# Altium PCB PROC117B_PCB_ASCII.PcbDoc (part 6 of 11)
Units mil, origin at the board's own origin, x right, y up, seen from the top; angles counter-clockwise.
Board outline 2480.32 x 3185.25 mil, 8 copper layers (Top Layer, L2_GND1, L3_SIG1, L4_PWR1, L5_PWR2, L6_SIG2, L7_GND2, Bottom Layer), stack 57.4 mil thick; 456 components, 292 nets, 7831 pads, 2905 vias.
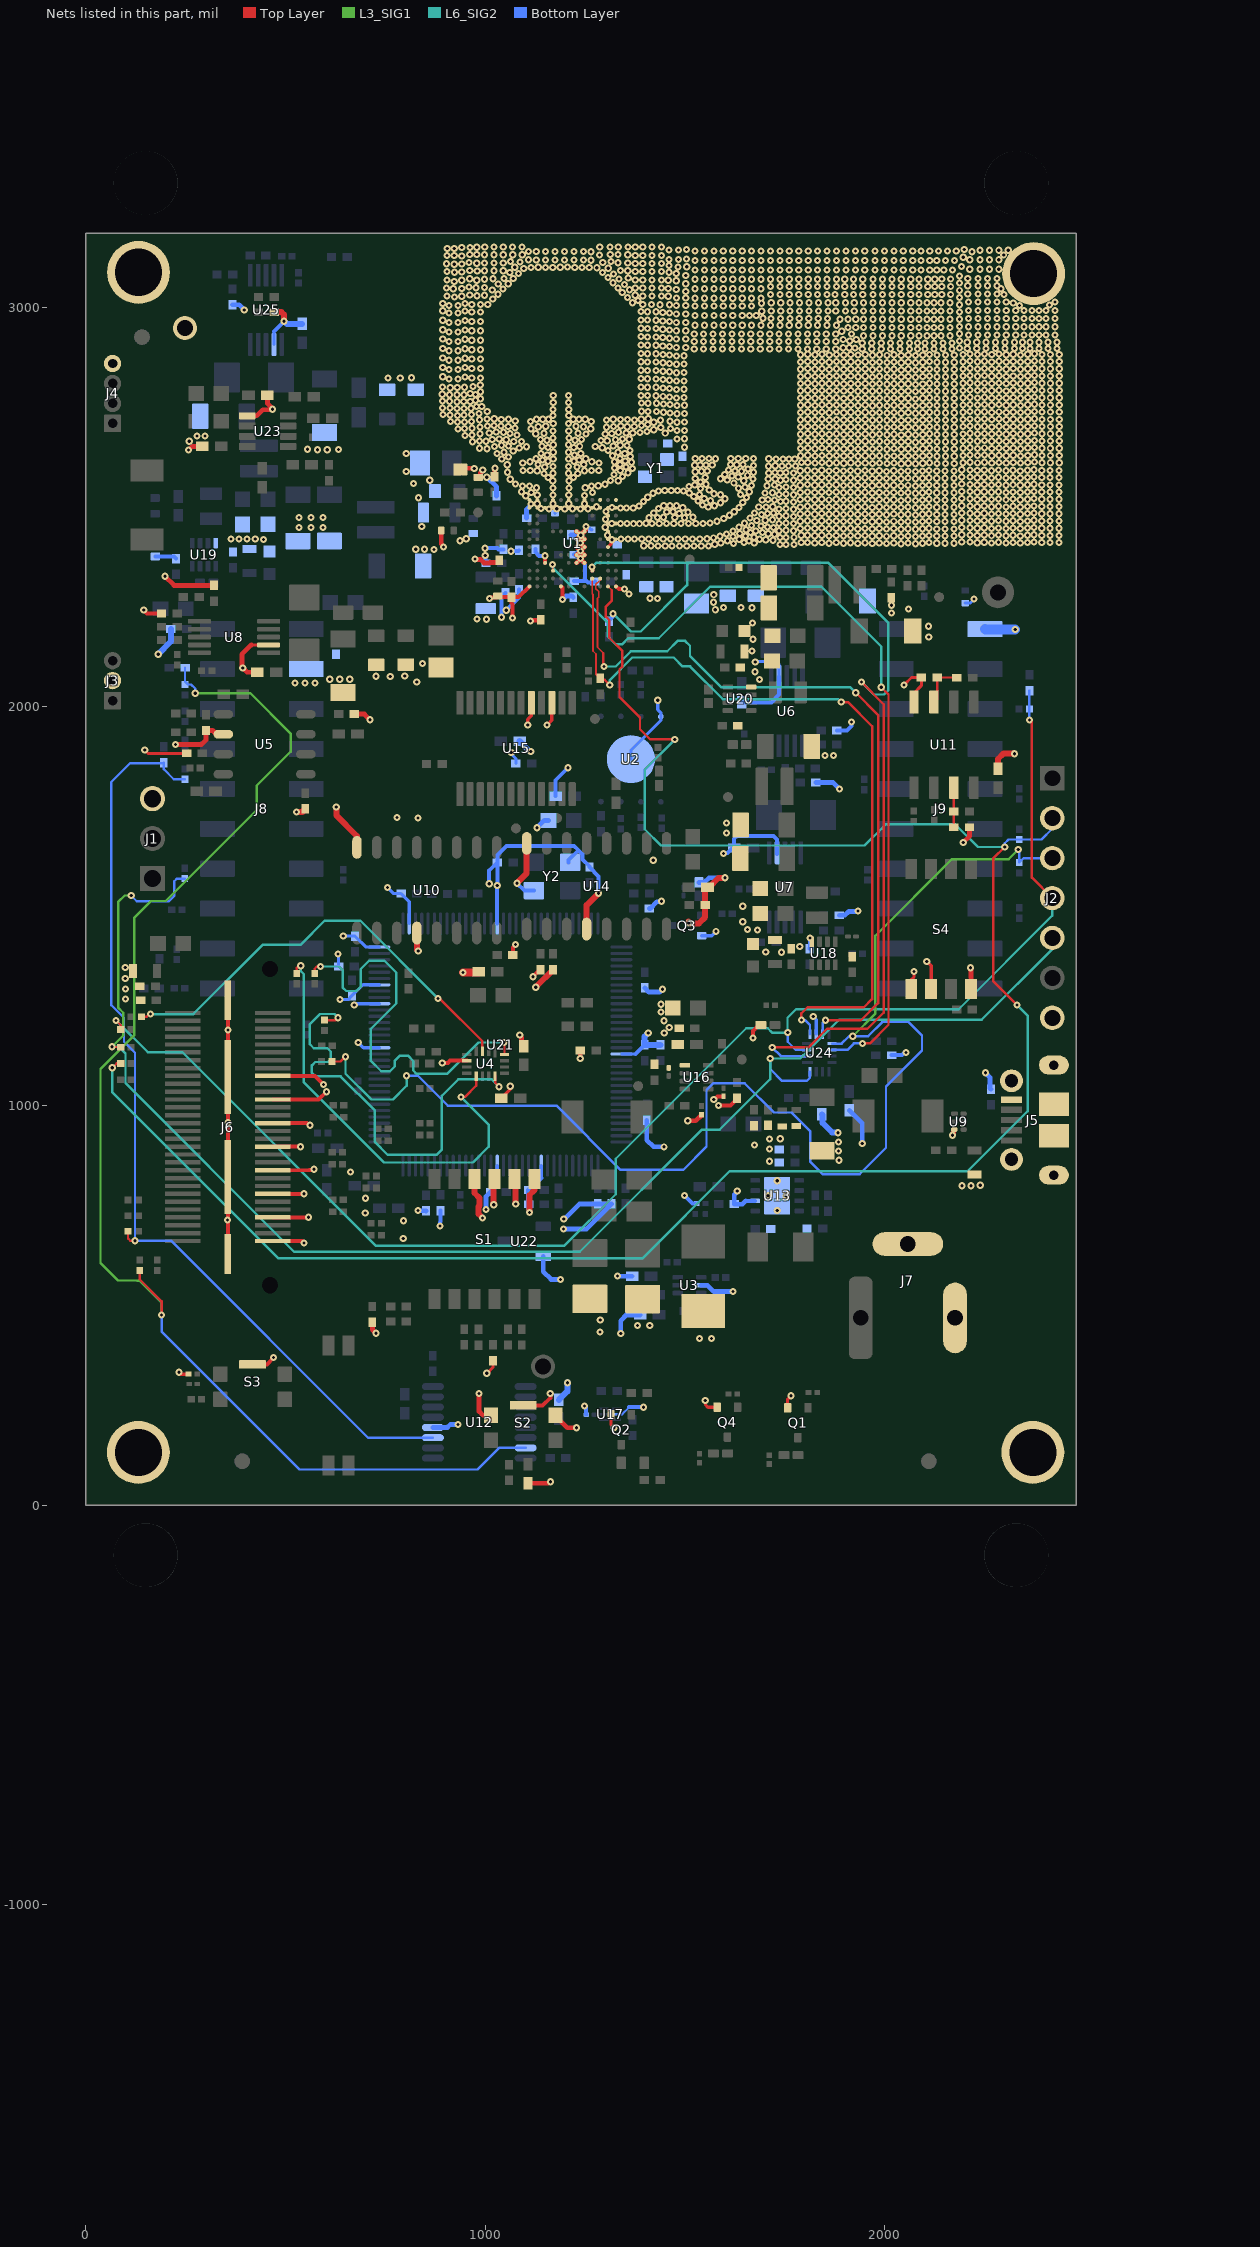
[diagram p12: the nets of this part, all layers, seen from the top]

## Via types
v1: diameter 18, hole 8, Top Layer to Bottom Layer, tented both sides, 2905 vias

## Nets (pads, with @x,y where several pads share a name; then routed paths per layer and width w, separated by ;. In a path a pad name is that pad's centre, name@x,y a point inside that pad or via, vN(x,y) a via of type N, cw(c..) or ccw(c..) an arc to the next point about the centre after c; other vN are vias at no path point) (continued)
DCA_LP_HOST_INTR_GPIO_0_LED: U1.J10 U24.10 | length 2189.6
  Top Layer w4: v1(1168.99,2355.28) 1168.97,2341.18 U1.J10@1170.05,2340.09
  Top Layer w6: v1(1944.68,1156.26) 1963.41,1156.26 2010.08,1202.93 2010.08,2029.8 v1(1991.83,2048.05)
  L6_SIG2 w6: v1(1168.99,2355.28) 1168.99,2348.04 1306.77,2210.26 1306.77,2176.04 1327.21,2155.6 1342.77,2155.6 1357.99,2170.82 1434.67,2170.82 1563.9,2300.05 1841.91,2300.05 1991.83,2150.13 v1(1991.83,2048.05)
  Bottom Layer w6: U24.10@1868.72,1140.1 1907.36,1140.1 1923.51,1156.26 v1(1944.68,1156.26)
DCA_LP_RS232_RX: R36.1 R61.1 R96.1 U12.3 | length 2393.1
  Top Layer w6: R61.1@105.65,686.13 105.65,667.89 111.44,662.1 122.94,662.1 v1(123.11,662.28)
  Bottom Layer w6: R36.1@248.36,1817.77 220.36,1817.77 195.06,1843.07 R96.1@195.06,1859.36 193.89,1858.18 111.24,1858.18 63.84,1810.79 63.84,1252.14 95.59,1220.39 95.59,1160.43 123.11,1132.91 v1(123.11,662.28) 213.53,662.28 706.94,168.86 U12.3@869.18,168.86
DCA_LP_RS232_TX: R35.1 R62.1 R95.1 U12.15 | length 3382.1
  Top Layer w6: R62.1@135.17,587.81 135.17,564.91 189.74,510.34 v1(189.74,476.22)
  L3_SIG1 w6: v1(189.74,476.22) 189.74,507.09 135.19,561.65 129.03,561.65 128.27,562.41 80.78,562.41 36.9,606.29 36.9,1092.15 121.06,1176.31 121.06,1470.58 163.31,1512.82 200.22,1512.82 427.95,1740.55 427.95,1801.75 513,1886.8 513,1932.1 412.07,2033.03 274.23,2033.03 v1(274.12,2032.93)
  Bottom Layer w6: v1(189.74,476.22) 189.74,434.55 534.95,89.34 980.78,89.34 1034.72,143.27 U12.15@1101.47,143.27 ; R95.1@248.55,2096.89 248.55,2062.57 256.19,2054.94 263.78,2054.94 274.12,2044.59 v1(274.12,2032.93)
DCA_LP_SPI_CLK: J2.5 R41.1 R146.1 U24.16 | length 3765.3
  Top Layer w6: v1(65.72,1147.92) 66.43,1147.2 86.8,1147.2 R41.1@87.52,1146.48
  L3_SIG1 w6: v1(65.72,1147.92) 93.94,1176.14 93.94,1232.98 80.95,1245.98 80.95,1510.25 97.37,1526.67 v1(113.77,1526.67)
  L6_SIG2 w6: v1(65.72,1147.92) 82.44,1147.92 99.31,1131.05 99.31,1056.82 521.73,634.4 1237.03,634.4 1542.95,940.33 1587.57,940.33 1714.04,1066.8 v1(1714.04,1118.37) 1789.34,1118.37 1886.92,1215.96 2243.71,1215.96 2420.67,1392.92 2420.67,1420.03 J2.5@2420.41,1420.3
  Bottom Layer w6: v1@113.77,1526.16 127.78,1512.14 208.16,1512.14 221.54,1525.52 221.54,1562.18 228.29,1568.93 R146.1@247.61,1568.93 ; v1(1714.04,1118.37) 1714.04,1091.97 1743.77,1062.24 1805.36,1062.24 1813.43,1070.32 1813.43,1084.81 U24.16@1813.6,1084.99
DCA_LP_SPI_CLK_I2C_SCL: R75.1 U1.D10 U24.2 | length 2666
  Top Layer w6: v1(1718.81,1146.13) 1809.89,1146.13 1856.53,1192.77 1957.59,1192.77 1998.13,1233.31 1998.13,2005.24 v1(1942.21,2061.17)
  Top Layer w10: v1(1267.99,2349.1) 1268.41,2348.69 1268.41,2340.16 U1.D10@1268.48,2340.09
  L6_SIG2 w6: v1(1267.99,2349.1) 1279.21,2360.31 1506.73,2360.31 ; v1(1320.35,2232.42) 1365,2187.76 1389.55,2187.76 1505.72,2303.93 1505.72,2359.3 1506.73,2360.31 ; v1(1942.21,2061.17) 1973.32,2030.05 1999.29,2030.05 2009.83,2040.6 2009.83,2209.21 1858.74,2360.31 1506.73,2360.31
  Bottom Layer w6: v1(1718.81,1146.13) 1740.59,1124.36 U24.2@1805.73,1124.36
  Bottom Layer w10: R75.1@1310.15,2213.57 1310.15,2215.54 1318.81,2224.21 1318.81,2230.89 v1(1320.35,2232.42)
DCA_LP_SPI_CS: J2.4 R39.1 R99.1 R140.2 U24.3 | length 3697.8
  Top Layer w6: v1(75.87,1213.57) 87.52,1201.92 R39.1@87.52,1191.19 ; v1(2362.9,1965.96) 2369.27,1959.58 2369.27,1571.44 J2.4@2420.41,1520.3
  L6_SIG2 w6: v1(75.87,1213.57) 155.52,1133.92 241.84,1133.92 725.74,650.03 1198.7,650.03 1327.12,778.45 1327.12,867.3 1653.97,1194.15 1707.77,1194.15 1718.72,1183.2 v1(1757.87,1183.2) 1757.2,1183.87 1757.2,1220.47 1778.66,1241.93 2186.17,1241.93 2420.41,1476.18 J2.4@2420.41,1520.3
  Bottom Layer w6: v1(1757.87,1183.2) 1757.87,1160.26 1778.03,1140.1 U24.3@1805.73,1140.1 ; v1(2362.9,1965.96) 2363.07,1966.13 R140.2@2363.07,1993.71 2363.07,2039.53 R99.1@2362.98,2039.62
DCA_LP_SPI_CS_I2C_SDA: R4.1 U1.D11 U24.5 | length 1994.7
  Top Layer w4: U1.D11@1268.48,2320.4 1268.48,2282.15 1270.23,2280.39 1270.23,2138.93 1277.64,2131.52
  Top Layer w6: 1277.64,2131.52 1277.64,2080.8 R4.1@1288.24,2070.19 1291.72,2066.72 1299.52,2066.72 v1(1312.25,2053.99) ; v1(1791.96,1214.7) 1791.96,1231.72 1807.23,1246.99 1948.89,1246.99 1969.17,1267.27 1969.17,1950.62 1908.84,2010.94 1891.94,2010.94 v1(1891.68,2011.2)
  L6_SIG2 w6: v1(1312.25,2053.99) 1312.39,2054.13 1312.39,2066.35 1368.56,2122.53 1472.29,2122.53 1494.45,2100.37 1513.33,2100.37 1595.14,2018.56 1884.32,2018.56 v1(1891.68,2011.2)
  Bottom Layer w6: v1(1791.96,1214.7) 1792.04,1214.61 1801.29,1214.61 1813.6,1202.31 U24.5@1813.6,1179.47
DCA_LP_SPI_MISO: J2.3 R53.2 R153.2 U24.9 | length 3361.7
  Top Layer w6: R53.2@616.38,1110.85 638.27,1110.85 650.32,1122.91 v1(650.47,1122.91)
  L3_SIG1 w6: v1(1920.55,1174.27) 1977.19,1230.91 1977.19,1425.84 2169.19,1617.84 2311.27,1617.84 v1(2335.12,1641.69)
  L6_SIG2 w6: v1(650.47,1122.91) 650.47,1080.39 715.07,1015.79 768.95,1015.79 803.44,1050.28 v1(803.44,1075.16)
  Bottom Layer w6: v1(803.44,1075.16) 831.81,1075.16 906.6,1000.36 1178.51,1000.36 1339.34,839.54 1496.16,839.54 1554.42,897.79 1554.42,1039.92 1570.68,1056.19 1650.22,1056.19 1723.24,983.17 1767.35,983.17 1814.68,935.84 1814.68,859.26 1844.88,829.06 1938.18,829.06 2004.02,894.91 2004.02,1048.7 2094.09,1138.76 2094.09,1176.19 2060,1210.27 1994.97,1210.27 1958.97,1174.27 v1(1920.55,1174.27) 1911.27,1174.27 1892.85,1155.85 U24.9@1868.72,1155.85 ; v1(2335.12,1641.69) 2337.72,1639.09 R153.2@2337.72,1609.25 2348.77,1620.3 J2.3@2420.41,1620.3
DCA_LP_SPI_MISO_REG_MODE: U1.C11 U24.7 | length 1948.9
  Top Layer w4: U1.C11@1288.16,2320.4 1288.16,2316.76 1277.24,2305.83 1277.24,2295.11 1284.43,2287.92 1284.43,2273.43 1281.49,2270.49 1281.49,2148.33 1296.01,2133.81
  Top Layer w6: 1296.01,2133.81 1296.01,2102.25 v1(1298.04,2100.22) ; v1(1852.7,1214.4) 1941.33,1214.4 1984.24,1257.31 1984.24,1978.36 v1(1928.01,2034.59)
  L6_SIG2 w6: v1(1298.04,2100.22) 1327.12,2100.22 1365.17,2138.26 1456,2138.26 1482.04,2164.31 1500.85,2164.31 1513.12,2152.03 1513.12,2126.69 1591.91,2047.9 1914.7,2047.9 v1(1928.01,2034.59)
  Bottom Layer w6: U24.7@1845.1,1179.47 1845.1,1206.97 1852.52,1214.4 v1(1852.7,1214.4)
DCA_LP_SPI_MOSI: J2.2 R52.1 R145.2 U1.B12 | length 5312
  Top Layer w4: U1.B12@1307.85,2300.72 1317.55,2291.02
  Top Layer w6: v1(66.37,1095.2) 77.85,1106.68 86.87,1106.68 R52.1@87.52,1106.03 ; 1317.55,2291.02 1317.55,2265.59 1302.35,2250.39 1302.35,2224.97 1310.85,2216.46 1310.85,2171.96 1343.67,2139.14 1343.67,2100.31 1336.53,2093.16 1336.53,2024.07 1387.84,1972.75 1387.84,1943.13 1413.39,1917.58 v1(1475.09,1917.58) ; v1(2301.12,1648.02) 2272.1,1618.99 2272.1,1312.66 v1(2332.2,1252.55)
  L6_SIG2 w6: v1(66.37,1095.2) 66.01,1094.84 66.01,1034.76 483,617.77 1393.73,617.77 1612.11,836.15 2208.27,836.15 2358.54,986.42 2358.54,1226.21 v1(2332.2,1252.55) ; v1(1475.09,1917.58) v1(1475.09,1917.58) 1399.58,1842 1399.58,1692.42 1440.22,1651.77 1950.32,1651.77 2003.39,1704.84 2177.37,1704.84 2234.2,1648.02 v1(2301.12,1648.02)
  Bottom Layer w6: v1(2301.12,1648.02) 2301.12,1657.58 2310.38,1666.84 R145.2@2337.72,1666.84 2393.54,1666.84 2420.41,1693.71 J2.2@2420.41,1720.3
DCA_TCK: R38.2 U4.16 | length 1050.4
  Top Layer w6: R38.2@573.4,1331.62 573.4,1343.13 579.23,1348.96 v1(587.84,1348.96) ; v1(1047.39,1158.6) 1048.51,1157.48 U4.16@1048.51,1128.64
  L6_SIG2 w6: v1(587.84,1348.96) 633.96,1348.96 643.26,1339.65 643.26,1296.54 652.28,1287.51 677.71,1287.51 688.16,1297.96 688.16,1342.08 709.32,1363.25 748.04,1363.25 777.94,1333.35 777.94,1256.85 714.04,1192.95 714.04,1112.57 739.97,1086.64 761.51,1086.64 774.04,1099.17 774.04,1113.16 786.48,1125.6 806.55,1125.6 819.85,1112.3 819.85,1088.29 828.09,1080.05 904.51,1080.05 983.07,1158.6 v1(1047.39,1158.6)
DCA_TDI: R37.1 U4.3 | length 1103.3
  Top Layer w6: R37.1@139.49,1223.18 152.37,1223.18 158.77,1229.58 v1(162.02,1229.58) ; v1(881.99,1268.92) 885.87,1268.92 993.02,1161.76 993.02,1136.89 U4.3@993.4,1136.51
  L6_SIG2 w6: v1(162.02,1229.58) 269.27,1229.58 442.52,1402.82 537.57,1402.82 598,1463.25 687.66,1463.25 v1(881.99,1268.92)
DCA_TDO: R34.2 U4.9 | length 1109.6
  Top Layer w6: R34.2@528.61,1331.62 528.61,1345.87 533.28,1350.54 v1(538.27,1350.54) ; v1(939.53,1022.2) 949.32,1022.2 977.65,1050.53 U4.9@977.65,1073.52
  L6_SIG2 w6: v1(538.27,1350.54) 538.27,1337.21 546.1,1329.38 546.1,1058.51 746.5,858.11 969.69,858.11 1008.85,897.27 1008.85,952.88 v1(939.53,1022.2)
DCA_TMS: R40.2 U4.12 | length 1118.6
  Top Layer w6: R40.2@597.77,1214.55 625.64,1214.55 v1(631.83,1220.73) ; U4.12@1024.89,1073.52 1024.89,1057.62 1034.89,1047.62 v1(1034.89,1047.54)
  L6_SIG2 w6: v1(631.83,1220.73) 622.54,1230.02 586.42,1230.02 561.1,1204.7 561.1,1153.96 570.78,1144.27 605.06,1144.27 613.57,1135.76 613.57,1116.92 606.25,1109.6 574.53,1109.6 566.17,1101.24 566.17,1082.1 574.74,1073.54 638.21,1073.54 723.86,987.89 723.86,909.38 756.03,877.21 878.47,877.21 891.83,890.57 891.83,1025.04 932.81,1066.02 1016.42,1066.02 v1(1034.89,1047.54)
EEPROM_A2: R161.1 R162.2 U11.3 | length 114.2
  Top Layer w6: U11.3@2123.96,2011.25 2131.84,2019.13 R162.2@2131.84,2072.49 2180.59,2072.49 R161.1@2181.24,2071.84
EEPROM_WPn: R157.1 R158.2 U11.7 | length 99.3
  Top Layer w6: R158.2@2173.7,1697.45 R157.1@2173.7,1737.31 2173.7,1796.42 U11.7@2173.96,1796.68
GND: C1.1 C2.2 C3.1 C4.1 C5.1 C6.2 C7.1 C8.1 C9.1 C10.1 C11.1 C12.1 C13.2 C14.1 C15.2 C16.1 C17.1 C18.1 C19.1 C20.1 C21.1 C22.1 C23.2 C24.1 C25.1 C26.1 C27.1 C28.1 C29.1 C30.2 C31.1 C32.1 C33.1 C34.2 C35.1 C36.2 C37.1 C38.1 C39.1 C40.2 C41.2 C42.2 C43.2 C44.2 C45.2 C46.1 C47.2 C48.2 C49.2 C50.2 C51.2 C52.1 C53.2 C54.1 C55.2 C56.2 C57.2 C58.2 C59.2 C60.2 C61.1 C62.2 C63.2 C64.1 C65.2 C66.2 C67.2 C68.1 C69.2 C70.2 C71.2 C72.2 C73.2 C74.2 C75.2 C76.2 C77.2 C78.1 C79.1 C80.1 C81.1 C82.1 C83.1 C84.2 C85.1 C86.1 C87.1 C88.2 C89.2 C90.2 C91.2 C92.2 C93.2 C94.2 C95.1 C96.1 C97.1 C98.1 C99.1 C101.1 C102.1 C103.1 C104.1 C105.1 C106.1 C107.1 C108.2 C109.2 C110.2 C111.1 C112.2 C113.1 C114.2 C115.2 C116.1 C118.1 C119.2 C120.2 C121.1 C122.1 C123.2 C124.1 C125.1 C126.1 C127.2 C128.2 C129.2 C130.1 C131.1 C132.2 C133.2 C134.2 C135.2 C136.2 C137.2 D4.2 D6.2 J1.3 J2.7 J3.2 J4.4 J5.5 J5.6 J5.7 J5.8 J5.9 J5.10 J5.11 J6.18 J6.24 J6.30 J6.36 J6.42 J6.48 J6.54 J6.60 J6.MP1 J6.MP2 J6.MP3 J6.MP4 J7.2 J7.3 J8.4 J9.2 pad.TH1 pad.TH2 pad.TH4 pad.TH9 Q1.2 Q2.2 Q3.2 Q4.2 R6.1 R11.1 R12.1 R33.1 R43.1 R57.2 R71.1 R72.1 R91.2 R101.1 R103.1 R113.1 R114.1 R116.1 R117.1 R120.1 R121.1 R131.1 R148.1 R150.1 R152.2 R158.1 R162.1 R177.1 R178.1 R180.1 R191.2 R194.2 R201.1 R205.1 R208.1 R215.2 R234.1 R239.1 S1.7 S1.8 S1.9 S1.10 S2.1 S2.2 S2.5 S3.5 S4.5 S4.6 S4.8 TP11.1 U1.A1 U1.A2 U1.A4 U1.A6 U1.A12 U1.B2 U1.B3 U1.B4 U1.B5 U1.B6 U1.B7 U1.C1 U1.C2 U1.D2 U1.E1 U1.E2 U1.E5 U1.E6 U1.E7 U1.E8 U1.E9 U1.F2 U1.F5 U1.F6 U1.F7 U1.F8 U1.F9 U1.G1 U1.G2 U1.H2 U1.H12 U1.J1 U1.J2 U1.K2 U1.K9 U1.L1 U1.L2 U1.M1 U1.M2 U1.M12 U2.4 U2.9 U3.2 U4.6 U5.2 U6.7 U7.7 U8.7 U9.3 U10.8 U10.12 U11.4 U12.4 U13.6 U13.9@1731.38,774.87 U14.8 U14.12 U15.3 U15.5 U16.1 U17.2 U18.8 U19.8 U20.8 U21.10 U21.17 U21.48 U21.55 U21.58 U21.64 U21.66 U21.80 U21.114 U22.2 U23.5 U24.6 U25.7 Y1.2 Y1.4 Y2.2 Y2.4 | length 10676
  Top Layer w8: v1(147.46,1890.73) 156.03,1882.16 252,1882.16 C37.1@252.79,1882.94 ; v1(233.45,332.65) 238.17,327.93 R215.2@257.37,327.93 ; 414.62,2154.08 U8.7@454.84,2154.08 ; v1(1004.31,330.03) 1004.97,330.03 1019.54,344.61 R208.1@1019.54,361.9 R208.1@1019.67,361.77 ; R6.1@1040.84,1019.14 1063.14,1041.45 v1(1063.14,1049.06) ; v1(1106.72,1953.37) 1106.63,1953.46 1106.63,1967.72 1115.82,1976.92 U15.5@1115.82,2009.1 ; v1(1155.01,1953.39) 1155.24,1953.39 1167,1965.14 U15.3@1167,2009.1 ; U1.B7@1307.85,2399.14 1307.85,2399.79 1315.82,2407.76 1315.82,2415.64 v1(1317.74,2417.55) ; Q2.2@1315.17,226.41 1315.17,201.12 v1(1322.52,193.78) ; v1(1551.48,261.63) 1552.2,260.9 1552.2,250.84 1557.84,245.2 Q4.2@1581.21,245.2 ; Q1.2@1757.47,243.61 1757.47,265.43 1766.01,273.98 v1(1766.01,274.05) ; v1(2048.84,2053.47) 2067.86,2072.49 R162.1@2092.47,2072.49 2092.47,2052.36 2073.96,2033.85 U11.4@2073.96,2011.25 ; S4.5@2067.14,1292.74 2067.03,1292.85 2067.03,1315.37 2073.97,1322.31 v1(2073.97,1336.47) ; v1@2106.34,1361.7 2117.14,1350.9 S4.6@2117.14,1292.74
  Top Layer w10: v1(144.91,2241.59) 153.69,2232.82 R116.1@189.51,2232.82 ; J6.MP4@355.62,629.36 J6.MP3@355.62,821.88 J6.MP2@355.62,1071.88 J6.MP1@355.62,1264.4 ; S3.5@417.49,352.46 453.46,352.46 470.07,369.07 v1(470.07,369.8) ; J6.60@468.42,661.44 541.24,661.44 v1(546.09,656.59) ; J6.54@468.42,720.5 557.79,720.5 v1(557.98,720.69) ; J6.48@468.42,779.55 546.4,779.55 v1(546.8,779.96) ; J6.42@468.42,838.61 558.84,838.61 559.78,839.55 569.62,839.55 v1(571.15,841.08) ; J6.36@468.42,897.66 537.72,897.66 v1(537.8,897.59) ; J6.30@468.42,956.72 554.02,956.72 559.36,951.38 v1(561.52,951.38) ; J6.24@468.42,1015.77 583.03,1015.77 v1(602.46,1035.21) ; J6.18@468.42,1074.83 574.15,1074.83 v1(595.34,1053.64) ; v1(892.85,1107.38) 906.87,1107.38 912.39,1112.89 U4.6@954.03,1112.89 ; v1(1010.9,2270.52) 1013.06,2270.52 1015.27,2272.74 1027.83,2272.74 C17.1@1031.69,2276.59 1034.64,2276.59 C17.1@1037.63,2273.6 ; C17.1@1038.5,2272.74 C17.1@1037.63,2273.6 ; v1(1068.7,2221.65) 1068.7,2256.68 1066.08,2259.29 C21.1@1066.08,2273.6 ; C88.2@1069.26,1377.59 1069.26,1396.63 1076.44,1403.81 v1(1076.44,1403.96) ; S2.5@1095.36,249.85 1144.17,249.85 1163.14,268.83 v1(1163.14,279.25) ; U1.M12@1111,2300.72 1083.88,2273.6 C21.1@1066.08,2273.6 ; v1(1119.71,1323.38) 1137.24,1340.91 C125.1@1138.59,1340.91 ; v1(1149.72,2377.41) 1150.3,2376.84 1150.3,2359.85 U1.K9@1150.37,2359.77 ; U1.H12@1190.49,2300.72 1193.67,2297.54 v1(1193.67,2267.68) ; v1(1238.14,1118.77) v1@1238.3,1118.93 ; C115.2@1238.3,1138.46 C115.2@1238.46,1138.62 ; U1.A12@1327.53,2300.72 1328.17,2300.72 1335.29,2293.61 1344.78,2293.61 v1@1346.69,2291.69 ; v1(1572.42,1015.4) 1574.04,1015.4 1581.4,1022.77 1595.94,1022.77 1596.77,1023.59 C50.2@1596.77,1023.74 ; v1(1584.55,1000.88) 1614.24,1000.88 1630.46,1017.09 C137.2@1630.46,1019.06 ; v1(1670.99,1169.88) 1670.99,1187.02 1686.34,1202.37 D6.2@1690.47,1202.37 ; C17.1@1037.63,2273.6 C21.1@1066.08,2273.6
  Top Layer w12: v1(198.25,2326.05) 221.09,2303.21 R117.1@321.43,2303.21 ; v1(224.65,1905.01) 289.91,1905.01 301.2,1916.3 C39.1@301.2,1939.79 ; v1(257.27,2641.93) 266.52,2651.2 C123.2@291.68,2651.2 ; C39.1@301.17,1939.82 317.55,1939.82 326.91,1930.45 U5.2@344.39,1930.45 ; U23.5@404.31,2727.79 427.64,2727.79 443,2743.15 466.57,2743.15 466.57,2747.07 454.71,2758.93 C132.2@454.71,2779.11 ; 414.62,2154.08 390.99,2130.45 390.99,2102.85 391.86,2101.98 391.86,2097.73 404.01,2085.59 C59.2@429.48,2085.59 ; R71.1@672.41,1980.88 697.62,1980.88 v1(711.57,1966.94) ; R205.1@717.37,458.04 717.68,457.73 717.68,439.42 726.77,430.33 v1(726.77,430.23) ; C3.1@890,2440.84 890,2406.99 895.74,2401.25 v1(895.74,2399.63) ; C23.2@937.73,2597.25 938.51,2596.47 972.05,2596.47 v1(972.83,2595.7) ; v1(974.42,2368.95) 975.57,2367.8 989.06,2367.8 997.44,2359.43 1010.84,2359.43 1012.25,2360.83 1031.39,2360.83 1035.23,2364.68 C26.1@1035.23,2366.65 ; C9.1@982.61,2573.88 985.56,2573.88 988.42,2576.74 988.42,2584.8 993.87,2590.25 v1(993.87,2591.88) ; v1(984.86,279.25) 984.83,234.55 994.14,225.24 S2.1@1014.65,225.24 ; C19.1@1023.28,2575.69 1023.98,2576.39 1023.98,2595.77 v1(1024.68,2596.47) ; v1(1086.66,1177.43) 1086.66,1175.81 1090.81,1171.66 1090.81,1155.37 C40.2@1096.63,1149.56 ; C53.2@1107.4,54.94 1158.29,54.94 1161.81,58.46 v1(1163.44,58.46) ; v1(1113.48,2214.32) 1114.87,2215.71 1138.04,2215.71 C7.1@1139.43,2217.11 ; S2.2@1176.07,224.1 1176.07,223.28 1187.78,211.56 1188.61,211.56 1206.18,193.99 v1(1228.56,193.99) ; U1.F9@1229.11,2359.77 1229.11,2359.82 1238.9,2369.62 v1@1238.9,2369.7 ; U1.F8@1229.11,2379.46 1229.11,2379.55 1238.86,2389.3 v1@1238.86,2389.5 ; U1.F5@1229.11,2438.51 U1.F5@1229.33,2438.51 ; U1.F8@1229.11,2379.46 v1@1238.9,2369.7 ; v1@1238.17,2409.73 1229.11,2418.79 1229.29,2418.83 v1@1239.13,2428.67 ; v1@1238.3,1118.93 C115.2@1238.3,1138.46 ; U1.E9@1248.79,2359.77 v1@1238.9,2369.7 ; v1(1252.48,2450.42) 1251.33,2449.27 1251.33,2441.05 U1.E5@1248.79,2438.51 1248.79,2438.33 1239.17,2428.71 v1(1239.36,2428.71) 1239.36,2428.49 1248.79,2419.06 U1.E6@1248.79,2418.83 1248.15,2418.83 1239.01,2409.69 v1(1238.17,2409.69) ; v1(1507.46,962.65) 1507.71,962.4 1520.32,962.4 ; 1522.46,962.4 1527.54,962.4 1541.9,976.75 R120.1@1541.9,977.54 ; R131.1@2017.19,2272.41 2017.33,2272.27 2017.33,2253.57 v1(2017.46,2253.43) ; v1(2170.48,926.11) 2170.48,927.74 2172.77,930.02 2172.77,940.51 2172.86,940.6 U9.3@2174.64,940.6 ; v1(2197.16,1659.6) 2213.07,1675.51 R158.1@2213.07,1697.45 ; v1(2215.39,1345.67) 2216.54,1344.53 2216.54,1320.84 2217.14,1320.24 S4.8@2217.14,1292.74 ; U1.F5@1229.33,2438.51 1239.13,2428.71 U1.F5@1229.33,2438.51 ; v1(1238.17,2409.69) 1248.75,2399.14 1248.7,2399.14 1239.21,2389.66 v1(1239.12,2389.66) v1@1238.86,2389.66 ; v1(1238.17,2409.69) 1238.21,2408.89 1229.11,2399.79 U1.F7@1229.11,2399.14 1229.37,2399.14 v1@1238.86,2389.66 ; v1@1238.86,2389.5 v1@1238.86,2389.66 ; v1@1238.86,2389.5 1248.79,2379.56 U1.E8@1248.79,2379.46 1248.74,2379.46 1238.98,2369.7 v1@1238.9,2369.7
  Top Layer w15: R148.1@471.89,2987.41 490.04,2987.41 496.26,2981.19 v1(496.26,2964.48) ; v1(527.69,1735.67) 528.26,1736.24 542.25,1736.24 545.4,1739.39 547.37,1739.39 549.71,1741.73 C38.1@549.71,1743.7 ; v1(627.33,1748) 627.33,1727.18 679.03,1675.48 U10.8@679.03,1647.18 ; U10.12@829.03,1432.62 828.92,1432.5 828.92,1391.34 v1(832.73,1387.53) ; S1.10@973.28,816.28 973.28,781.68 986.2,768.76 986.2,750.12 983.59,747.52 983.59,729.05 v1(993.61,719.03) ; v1(1021.59,752.2) 1021.59,814.59 S1.9@1023.28,816.28 ; S1.8@1073.28,816.28 1076.52,813.04 v1(1076.52,754.22) ; v1(1079.52,1557.19) 1104.22,1581.9 U14.8@1104.22,1657.18 ; v1(1111.18,732.94) 1111.18,776.68 1123.28,788.78 S1.7@1123.28,816.28 ; v1(1126.68,1297.08) 1126.68,1297.54 C124.1@1170.32,1341.17 ; U14.12@1254.22,1442.61 1254.22,1502.29 v1(1284.32,1532.38) ; v1(1509.88,1457.51) 1509.88,1461.41 1514.27,1457.02 1535.76,1457.02 1551.03,1472.3 C90.2@1551.03,1502.8 1551.03,1543.07 1555.34,1547.38 C89.2@1556.89,1547.38 1560.82,1547.38 1583.84,1570.4 1600.48,1570.4 v1(1601.06,1570.97) ; C65.2@2284.36,1843.87 2284.36,1868.55 2297.56,1881.75 v1(2325.76,1881.75)
  Top Layer w20: v1(944.63,1334.11) 982.37,1334.11 C75.2@983.55,1335.29
  Bottom Layer w6: U17.2@1328.64,227.49 1343.11,227.49 1360.92,245.3
  Bottom Layer w8: U25.7@471.17,2906.62 471.17,2939.39 ; v1(631.31,1379.88) 633.04,1378.15 R194.2@633.04,1348.51 ; v1(636.57,1266.08) 657.43,1266.08 R234.1@666.49,1275.15 694.27,1302.92 U21.58@735.06,1302.92 ; v1(644.86,1425.53) 651.9,1425.53 652.37,1425.07 R191.2@674.18,1425.07 701.83,1397.41 U21.64@735.06,1397.41 ; v1(672.2,1252.06) 675.81,1255.67 U21.55@735.06,1255.67 ; v1(682.29,1158.3) 695.16,1145.44 U21.48@735.06,1145.44 ; v1(755.84,1546.31) 770.7,1531.47 C95.1@789.57,1531.47 809.87,1511.18 U21.66@809.87,1456.46 ; 1030.34,800.99 U21.17@1030.34,850.16 ; v1(1065.3,1884.79) 1065.3,1881.48 1077.05,1869.73 R91.2@1077.05,1857.39 ; C99.1@1108.96,753.63 C99.1@1108.87,753.54 C99.1@1110.03,752.38 ; C102.1@1108.96,789.42 C102.1@1110.47,789.42 ; v1@1110.03,734.09 v1(1111.18,732.94) ; 1140.58,819.52 U21.10@1140.58,850.16 ; C22.1@1174.63,2483.89 1177.33,2486.59 1177.33,2493.11 v1(1179.24,2495.02) ; v1(1252.48,2450.42) 1254.39,2448.51 1259.12,2448.51 1265.15,2442.47 C18.1@1267.12,2442.47 ; U21.114@1341.36,1129.69 1376.79,1129.69 ; U2.9@1365.12,1868.19 1365.12,1889.77 1440.12,1964.77 U2.4@1440.12,1974.49 1440.12,1984.22 1432.24,1992.09 v1(1432.24,2015.56) ; C126.1@1438.64,1152.5 C126.1@1438.99,1152.86 ; Q3.2@1542.43,1425.91 1567.39,1425.91 v1(1578.35,1436.88) ; v1(1676.27,2111.72) 1677.16,2112.61 1729.2,2112.61 1735.92,2105.89 U6.7@1735.92,2074.85 ; v1(1821.61,1223.93) 1829.35,1216.2 U24.6@1829.35,1179.47 ; C78.1@2202.3,2258.84 2202.37,2258.91 2214.34,2258.91 v1(2224.49,2269.05)
  Bottom Layer w10: R121.1@174.34,2375.85 220.74,2375.85 225.59,2371.01 R178.1@225.59,2370.27 ; 471.17,2939.39 v1(496.26,2964.48) ; v1(886.85,699) 886.85,708.38 888.65,710.18 C113.1@888.65,737.61 ; v1(999.92,2396.26) 1031.08,2396.26 1033.74,2393.59 C12.1@1046.09,2393.59 ; v1(1000.2,2377.88) 1001.18,2376.9 1001.18,2359.65 C8.1@1002.15,2358.67 ; v1(1010.12,1556.13) 1010.12,1588.66 C98.1@1030.67,1609.21 ; U21.80@1030.34,1456.46 v1(1030.32,1551.43) 1030.67,1551.77 C98.1@1030.67,1609.21 ; v1(1040.85,2223.4) 1040.85,2273.85 C30.2@1051.43,2284.43 ; v1(1052.71,2240.84) 1084.65,2272.78 C25.1@1084.65,2292.85 ; v1(1064.67,2388.54) 1066.01,2389.88 1083.45,2389.88 C11.1@1084.79,2391.22 ; v1(1079.52,1557.19) 1098.09,1538.63 1121.96,1538.63 Y2.4@1122.2,1538.88 ; C6.2@1125.93,2394.21 1125.93,2386.57 1135.09,2377.41 v1(1149.72,2377.41) ; C34.2@1176.58,1775.36 1176.58,1815.25 v1(1207.91,1846.58) ; Y2.2@1208.82,1609.74 1208.82,1615.2 1233.57,1639.95 ; C45.2@1223.1,2313.75 1254.07,2313.75 ; C29.1@1223.1,2380.12 C29.1@1225.07,2380.12 ; v1(1239.12,2389.66) 1237.21,2387.75 1232.7,2387.75 C29.1@1225.07,2380.12 ; v1(1249.2,248.33) 1253.12,244.42 1253.12,226.66 1253.29,226.49 C52.1@1253.75,226.49 ; C28.1@1274.59,2312.73 1271.83,2309.97 1257.85,2309.97 1254.07,2313.75 ; v1(1284.32,1532.38) 1284.32,1574.66 C97.1@1261.04,1597.93 1261.04,1599.9 1243.92,1617.02 1243.92,1629.59 1233.57,1639.95 ; 1360.92,245.3 v1(1396.81,245.3) ; 1376.79,1129.69 C127.2@1399.6,1152.5 ; v1(1499.67,775.54) 1519.7,755.51 R201.1@1529.65,755.51 ; v1(1597.32,1631.58) 1598.85,1633.11 1607.05,1633.11 1619.57,1645.63 C58.2@1623.51,1645.63 1623.58,1645.7 1623.58,1668.75 1630.98,1676.14 1721.82,1676.14 1731.11,1666.85 U7.7@1731.11,1630.46 ; R11.1@1623.82,753.81 R11.1@1623.93,753.71 ; v1@1631.4,785.16 v1(1631.4,786.79) ; C57.2@1642.68,2010.36 1716.69,2010.36 1735.92,2029.59 U6.7@1735.92,2074.85 ; 1652.64,762.08 U13.6@1676.26,762.08 ; R113.1@1812.67,1393.78 1813.16,1394.27 1813.16,1419.42 v1(1813.65,1419.91) ; R103.1@1880.65,1940.09 1906.04,1940.09 1917.23,1951.28 v1(1917.23,1961.3) ; R152.2@2017.89,1126.65 2044.14,1126.65 2050.69,1133.2 v1(2053.97,1133.2) ; C98.1@1030.67,1609.21 1030.67,1627.76 1053.59,1650.67 1222.84,1650.67 1233.57,1639.95 ; C29.1@1225.07,2380.12 1233.96,2371.23 1237.4,2371.23 1238.93,2369.7 1238.93,2367.54 1249.99,2356.47 1249.99,2317.82 1254.07,2313.75
  Bottom Layer w12: R150.1@367.15,3006.08 384,3006.08 v1(396.94,2993.14) ; v1(832.18,737.91) 832.8,737.28 851.46,737.28 C114.2@852.08,736.65 ; U12.4@869.18,194.46 905.65,194.46 913.36,202.17 v1(932.24,202.17) ; v1(1002.24,740.51) 1001.98,740.76 1001.98,772.63 C116.1@1013.86,784.51 1030.34,800.99 ; v1(1004.31,2574.08) 1028.73,2549.67 C101.1@1028.73,2528.18 C101.1@1028.73,2527.2 ; C4.1@1103.73,2471.28 1103.73,2493.38 1115.05,2504.69 v1(1115.05,2507.4) ; C99.1@1108.96,753.63 C102.1@1108.96,789.42 ; v1@1110.03,734.09 C99.1@1110.03,752.38 ; C102.1@1110.47,789.42 1140.58,819.52 ; v1(1129.67,1696.29) 1148.06,1714.68 C35.1@1158.79,1714.68 ; U22.2@1145.72,623.16 1145.72,584.57 1165.17,565.12 v1(1188.86,565.12) ; v1(1193.67,2267.68) 1193.78,2267.68 1202.72,2276.62 1217.16,2276.62 C16.1@1220.59,2273.19 ; v1(1196.64,691.76) 1254.43,691.76 C118.1@1316.92,754.25 R239.1@1282.09,754.25 1236.72,754.25 1199.04,716.58 v1(1197.07,716.58) ; C5.1@1215,2429.93 1215.6,2429.32 1238.75,2429.32 v1(1239.36,2428.71) 1238.77,2428.12 1238.77,2410.28 v1(1238.17,2409.69) ; v1(1331.47,573.52) 1333.76,573.52 1333.97,573.31 C36.2@1368.18,573.31 ; v1@1338.87,429.28 v1(1339.64,430.06) 1339.64,461.85 1354.04,476.26 R57.2@1388.21,476.26 ; C108.2@1399.6,1295.15 1410.01,1284.74 1437.03,1284.74 v1(1444.1,1291.81) ; C106.1@1404.89,964.07 1404.89,914.28 1421.96,897.22 v1(1448.18,897.22) ; C94.2@1411.42,1494 1413.39,1494 1430.27,1510.88 1440.2,1510.88 v1(1441.34,1512.03) ; R177.1@1535.32,1559.42 1549.24,1559.42 1560.8,1570.97 v1(1601.06,1570.97) ; U3.2@1540.92,550.63 1556.77,550.63 1572.76,534.64 1620.7,534.64 v1(1620.91,534.84) ; R11.1@1623.82,753.81 1623.82,777.58 v1@1631.4,785.16 ; R11.1@1623.93,753.71 1644.27,753.71 1652.64,762.08 ; R101.1@1828.29,1809.73 1870.91,1809.73 v1(1887.54,1793.1) ; R114.1@1886.82,1477.16 1901.14,1477.16 1910.55,1486.58 1932.84,1486.58 v1(1933.99,1487.72) ; R33.1@1912.13,988.51 1944.27,956.37 v1(1944.27,905.87) ; v1(2253.09,1082.54) 2264.27,1071.36 2264.27,1043.92 R72.1@2266.65,1041.55
  Bottom Layer w15: v1(181.28,2130.71) 213.17,2162.6 C76.2@213.17,2194.19 ; v1(496.26,2964.48) 497.07,2964.48 503.51,2958.03 C133.2@541.6,2958.03 ; C91.2@1086.42,1913.02 1112.51,1886.93 v1(1114.48,1886.93) ; C41.2@1184.91,263.55 C41.2@1184.63,263.82 1205.92,285.12 v1(1205.92,306.49) ; v1(1408.64,1182.63) 1399.6,1173.59 C127.2@1399.6,1152.5 C126.1@1438.64,1152.5 ; C2.2@1843.46,978.72 1845.01,977.17 1845.01,957.1 1868.85,933.26 1883.41,933.26 v1(1883.99,932.69)
  Bottom Layer w25: J9.2@2252.05,2193.63 2253.14,2192.54 v1(2327.5,2192.54)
